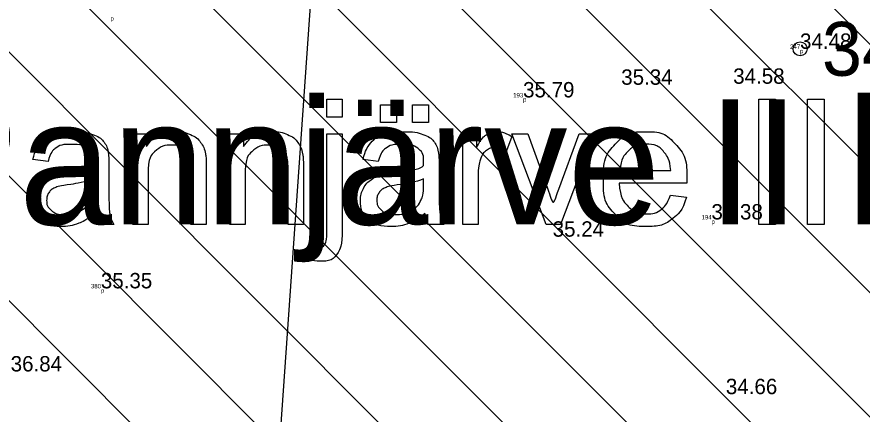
# Model space of a CAD drawing. Extents: x 700746 to 706058, y 6570320 to 6580460.
# Drawn here: x 702922.07 to 702960.58, y 6577287.8 to 6577305.88 of the extents above; entities that cross this region are included whole.
import ezdxf

# ---------------------------------------------------------------- set-up
doc = ezdxf.new("R2010")
doc.units = 0
for name, color, linetype in [('Kaevandatud ala', 7, 'Continuous'), ('KORGUS-EH2000', 7, 'Continuous'), ('Lamami horisontaal_EH2000', 7, 'Continuous'), ('MOOTKOOD', 7, 'Continuous'), ('MOOTKORG-EH2000', 7, 'Continuous'), ('MOOTNR', 7, 'Continuous'), ('VORMISTUS', 7, 'Continuous')]:
    doc.layers.add(name, color=color, linetype=linetype)

msp = doc.modelspace()

# ---------------------------------------------------------------- linework, layer by layer
at = {"layer": 'Kaevandatud ala'}
for p, q in [((702913.595, 6577351.973), (703042.537, 6577223.031)), ((702910.387, 6577349.524), (703039.613, 6577220.299)), ((702906.791, 6577347.464), (703036.689, 6577217.566)), ((702902.985, 6577345.613), (703032.499, 6577216.099)), ((702900.071, 6577342.869), (703027.542, 6577215.399)), ((702898.09, 6577339.194), (703023.191, 6577214.093)), ((702896.564, 6577335.063), (703018.039, 6577213.588)), ((702895.536, 6577330.434), (702988.663, 6577237.307)), ((702892.53, 6577327.783), (702983.517, 6577236.796)), ((702890.873, 6577323.784), (702978.651, 6577236.006))]:
    msp.add_line(p, q, dxfattribs=at)
at = {"layer": 'KORGUS-EH2000'}
msp.add_circle((702957.754, 6577304.422), 0.32, dxfattribs=at)
at = {"layer": 'Lamami horisontaal_EH2000'}
msp.add_lwpolyline([(702938.178, 6577345.551), (702932.405, 6577263.326)], dxfattribs=at)
at = {"layer": 'VORMISTUS'}
for points in [[(702936.193, 6577301.316), (702936.193, 6577302.129), (702936.893, 6577302.129), (702936.893, 6577301.316), (702936.193, 6577301.316)], [(702955.883, 6577296.429), (702955.883, 6577302.129), (702956.639, 6577302.129), (702956.639, 6577296.429), (702955.883, 6577296.429)], [(702958.094, 6577296.429), (702958.094, 6577302.129), (702958.85, 6577302.129), (702958.85, 6577296.429), (702958.094, 6577296.429)], [(702938.64, 6577301.073), (702938.64, 6577301.868), (702939.369, 6577301.868), (702939.369, 6577301.073), (702938.64, 6577301.073)], [(702940.091, 6577301.073), (702940.091, 6577301.868), (702940.82, 6577301.868), (702940.82, 6577301.073), (702940.091, 6577301.073)], [(702927.344, 6577296.429), (702927.344, 6577300.56), (702927.974, 6577300.56), (702927.974, 6577299.973)], [(702931.771, 6577296.429), (702931.771, 6577300.56), (702932.401, 6577300.56), (702932.401, 6577299.973)], [(702936.193, 6577296.22), (702936.193, 6577300.56), (702936.893, 6577300.56), (702936.893, 6577296.206)], [(702942.384, 6577296.429), (702942.384, 6577300.56), (702943.014, 6577300.56), (702943.014, 6577299.934)], [(702944.626, 6577300.428), (702944.381, 6577299.78)], [(702946.182, 6577296.429), (702944.618, 6577300.56), (702945.356, 6577300.56), (702946.241, 6577298.086)], [(702946.766, 6577298.039), (702947.682, 6577300.56), (702948.402, 6577300.56), (702946.839, 6577296.429), (702946.182, 6577296.429)], [(702923.486, 6577299.287), (702922.799, 6577299.378)], [(702938.535, 6577299.287), (702937.849, 6577299.378)], [(702926.258, 6577299.092), (702926.258, 6577298.159)], [(702930.698, 6577298.968), (702930.698, 6577296.429), (702929.998, 6577296.429), (702929.998, 6577298.939)], [(702935.125, 6577298.968), (702935.125, 6577296.429), (702934.425, 6577296.429), (702934.425, 6577298.939)], [(702941.307, 6577299.092), (702941.307, 6577298.159)], [(702949.553, 6577298.888), (702951.86, 6577298.888)], [(702925.55, 6577298.244), (702925.554, 6577298.501)], [(702928.043, 6577298.683), (702928.043, 6577296.429), (702927.344, 6577296.429)], [(702932.47, 6577298.683), (702932.47, 6577296.429), (702931.771, 6577296.429)], [(702940.599, 6577298.244), (702940.603, 6577298.501)], [(702943.084, 6577298.592), (702943.084, 6577296.429), (702942.384, 6577296.429)], [(702952.595, 6577298.314), (702949.514, 6577298.314)], [(702951.852, 6577297.762), (702952.575, 6577297.671)], [(702926.479, 6577296.429), (702925.749, 6577296.429)], [(702941.529, 6577296.429), (702940.799, 6577296.429)], [(702935.307, 6577294.83), (702935.436, 6577295.423)]]:
    msp.add_lwpolyline(points, dxfattribs=at)
for points, degree in [([(702922.799, 6577299.378), (702922.893, 6577299.818), (702923.106, 6577300.089), (702923.32, 6577300.359), (702923.724, 6577300.505), (702924.128, 6577300.651), (702924.661, 6577300.651), (702925.189, 6577300.651), (702925.519, 6577300.527), (702925.85, 6577300.402), (702926.005, 6577300.214), (702926.161, 6577300.025), (702926.223, 6577299.737), (702926.258, 6577299.558), (702926.258, 6577299.092)], 3), ([(702927.974, 6577299.973), (702928.428, 6577300.651), (702929.287, 6577300.651), (702929.66, 6577300.651), (702929.973, 6577300.517), (702930.286, 6577300.383), (702930.441, 6577300.165), (702930.597, 6577299.948), (702930.659, 6577299.648), (702930.698, 6577299.454), (702930.698, 6577298.968)], 3), ([(702932.401, 6577299.973), (702932.855, 6577300.651), (702933.714, 6577300.651), (702934.087, 6577300.651), (702934.4, 6577300.517), (702934.713, 6577300.383), (702934.868, 6577300.165), (702935.024, 6577299.948), (702935.086, 6577299.648), (702935.125, 6577299.454), (702935.125, 6577298.968)], 3), ([(702937.849, 6577299.378), (702937.942, 6577299.818), (702938.156, 6577300.089), (702938.369, 6577300.359), (702938.774, 6577300.505), (702939.178, 6577300.651), (702939.71, 6577300.651), (702940.239, 6577300.651), (702940.569, 6577300.527), (702940.899, 6577300.402), (702941.054, 6577300.214), (702941.21, 6577300.025), (702941.272, 6577299.737), (702941.307, 6577299.558), (702941.307, 6577299.092)], 3), ([(702943.014, 6577299.934), (702943.255, 6577300.372), (702943.459, 6577300.512), (702943.663, 6577300.651), (702943.908, 6577300.651), (702944.261, 6577300.651), (702944.626, 6577300.428)], 3), ([(702952.575, 6577297.671), (702952.404, 6577297.037), (702951.941, 6577296.687), (702951.479, 6577296.337), (702950.76, 6577296.337), (702949.854, 6577296.337), (702949.323, 6577296.895), (702948.793, 6577297.453), (702948.793, 6577298.459), (702948.793, 6577299.501), (702949.329, 6577300.076), (702949.866, 6577300.651), (702950.721, 6577300.651), (702951.549, 6577300.651), (702952.074, 6577300.087), (702952.598, 6577299.524), (702952.598, 6577298.501), (702952.598, 6577298.438), (702952.595, 6577298.314)], 3), ([(702925.61, 6577296.937), (702925.22, 6577296.608), (702924.86, 6577296.473), (702924.501, 6577296.337), (702924.089, 6577296.337), (702923.409, 6577296.337), (702923.043, 6577296.669), (702922.678, 6577297.001), (702922.678, 6577297.518), (702922.678, 6577297.821), (702922.816, 6577298.071), (702922.954, 6577298.322), (702923.177, 6577298.473), (702923.401, 6577298.625), (702923.681, 6577298.703), (702923.887, 6577298.757), (702924.302, 6577298.807), (702925.15, 6577298.908), (702925.55, 6577299.048), (702925.554, 6577299.193), (702925.554, 6577299.231), (702925.554, 6577299.66), (702925.356, 6577299.836), (702925.088, 6577300.074), (702924.561, 6577300.074), (702924.068, 6577300.074), (702923.833, 6577299.9), (702923.598, 6577299.727), (702923.486, 6577299.287)], 3), ([(702929.998, 6577298.939), (702929.998, 6577299.367), (702929.917, 6577299.579), (702929.835, 6577299.791), (702929.627, 6577299.917), (702929.419, 6577300.043), (702929.139, 6577300.043), (702928.692, 6577300.043), (702928.368, 6577299.759), (702928.043, 6577299.476), (702928.043, 6577298.683)], 3), ([(702934.425, 6577298.939), (702934.425, 6577299.367), (702934.344, 6577299.579), (702934.262, 6577299.791), (702934.054, 6577299.917), (702933.846, 6577300.043), (702933.566, 6577300.043), (702933.119, 6577300.043), (702932.795, 6577299.759), (702932.47, 6577299.476), (702932.47, 6577298.683)], 3), ([(702940.66, 6577296.937), (702940.269, 6577296.608), (702939.91, 6577296.473), (702939.55, 6577296.337), (702939.138, 6577296.337), (702938.458, 6577296.337), (702938.093, 6577296.669), (702937.727, 6577297.001), (702937.727, 6577297.518), (702937.727, 6577297.821), (702937.865, 6577298.071), (702938.003, 6577298.322), (702938.227, 6577298.473), (702938.45, 6577298.625), (702938.73, 6577298.703), (702938.936, 6577298.757), (702939.352, 6577298.807), (702940.199, 6577298.908), (702940.599, 6577299.048), (702940.603, 6577299.193), (702940.603, 6577299.231), (702940.603, 6577299.66), (702940.405, 6577299.836), (702940.138, 6577300.074), (702939.61, 6577300.074), (702939.117, 6577300.074), (702938.883, 6577299.9), (702938.648, 6577299.727), (702938.535, 6577299.287)], 3), ([(702951.86, 6577298.888), (702951.813, 6577299.41), (702951.595, 6577299.672), (702951.261, 6577300.078), (702950.728, 6577300.078), (702950.245, 6577300.078), (702949.917, 6577299.754), (702949.588, 6577299.43), (702949.553, 6577298.888)], 3), ([(702944.381, 6577299.78), (702944.126, 6577299.93), (702943.87, 6577299.93), (702943.642, 6577299.93), (702943.46, 6577299.792), (702943.278, 6577299.654), (702943.201, 6577299.409), (702943.084, 6577299.035), (702943.084, 6577298.592)], 3), ([(702925.554, 6577298.501), (702925.172, 6577298.345), (702924.41, 6577298.237), (702923.978, 6577298.175), (702923.799, 6577298.097), (702923.62, 6577298.019), (702923.522, 6577297.87), (702923.425, 6577297.72), (702923.425, 6577297.537), (702923.425, 6577297.258), (702923.637, 6577297.071), (702923.848, 6577296.885), (702924.256, 6577296.885), (702924.66, 6577296.885), (702924.975, 6577297.062), (702925.29, 6577297.238), (702925.437, 6577297.545), (702925.55, 6577297.782), (702925.55, 6577298.244)], 3), ([(702940.603, 6577298.501), (702940.222, 6577298.345), (702939.459, 6577298.237), (702939.027, 6577298.175), (702938.848, 6577298.097), (702938.669, 6577298.019), (702938.572, 6577297.87), (702938.474, 6577297.72), (702938.474, 6577297.537), (702938.474, 6577297.258), (702938.686, 6577297.071), (702938.898, 6577296.885), (702939.306, 6577296.885), (702939.71, 6577296.885), (702940.024, 6577297.062), (702940.339, 6577297.238), (702940.487, 6577297.545), (702940.599, 6577297.782), (702940.599, 6577298.244)], 3), ([(702926.258, 6577298.159), (702926.258, 6577297.184), (702926.302, 6577296.925), (702926.347, 6577296.666), (702926.479, 6577296.429)], 3), ([(702941.307, 6577298.159), (702941.307, 6577297.184), (702941.352, 6577296.925), (702941.396, 6577296.666), (702941.529, 6577296.429)], 3), ([(702946.241, 6577298.086), (702946.385, 6577297.685), (702946.505, 6577297.253), (702946.599, 6577297.58), (702946.766, 6577298.039)], 3), ([(702949.514, 6577298.314), (702949.553, 6577297.634), (702949.899, 6577297.272), (702950.245, 6577296.911), (702950.763, 6577296.911), (702951.148, 6577296.911), (702951.42, 6577297.114), (702951.693, 6577297.317), (702951.852, 6577297.762)], 3), ([(702925.749, 6577296.429), (702925.641, 6577296.646), (702925.61, 6577296.937)], 2), ([(702940.799, 6577296.429), (702940.691, 6577296.646), (702940.66, 6577296.937)], 2), ([(702936.893, 6577296.206), (702936.893, 6577295.444), (702936.695, 6577295.145), (702936.442, 6577294.756), (702935.855, 6577294.756), (702935.571, 6577294.756), (702935.307, 6577294.83)], 3), ([(702935.436, 6577295.423), (702935.647, 6577295.368), (702935.768, 6577295.368), (702935.982, 6577295.368), (702936.088, 6577295.51), (702936.193, 6577295.652), (702936.193, 6577296.22)], 3)]:
    msp.add_open_spline(points, degree=degree, dxfattribs=at)

# ---------------------------------------------------------------- texts
at = {"layer": 'KORGUS-EH2000'}
msp.add_text('34,48', height=2.45, dxfattribs=at).set_placement((702958.754, 6577303.197))
at = {"layer": 'MOOTKOOD'}
for p in [(702926.332, 6577305.702), (702957.754, 6577304.222), (702945.133, 6577302.011), (702953.717, 6577296.455), (702925.894, 6577293.32)]:
    msp.add_text('p', height=0.2, dxfattribs=at).set_placement(p)
at = {"layer": 'MOOTKORG-EH2000'}
for s, p in [('34.48', (702957.754, 6577304.422)), ('35.34', (702949.606, 6577302.787)), ('34.58', (702954.708, 6577302.832)), ('35.79', (702945.133, 6577302.211)), ('34.38', (702953.717, 6577296.655)), ('35.24', (702946.482, 6577295.872)), ('35.35', (702925.894, 6577293.52)), ('36.84', (702921.785, 6577289.737)), ('34.66', (702954.374, 6577288.703))]:
    msp.add_text(s, height=0.7, dxfattribs=at).set_placement(p)
at = {"layer": 'MOOTNR'}
for s, p in [('247', (702957.301, 6577304.422)), ('193', (702944.68, 6577302.211)), ('194', (702953.265, 6577296.655)), ('380', (702925.441, 6577293.52))]:
    msp.add_text(s, height=0.2, dxfattribs=at).set_placement(p)
at = {"layer": 'VORMISTUS'}
msp.add_text('Pannjärve II liivakarjäär', height=5.7, dxfattribs=at).set_placement((702917.078, 6577296.429))

doc.saveas('drawing.dxf')
